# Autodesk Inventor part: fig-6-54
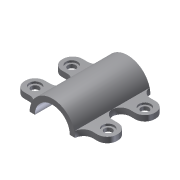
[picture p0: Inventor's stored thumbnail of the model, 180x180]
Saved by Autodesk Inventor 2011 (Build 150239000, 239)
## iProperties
Created: 2004-05
Part Number: fig-6-54
Document SubType Name: Modeling
Designer: CADCIM Technologies
Manufacturer: Standard
Standards Organization: Custom
Density: 1 g/cm^3
Author: CADCIM Technologies
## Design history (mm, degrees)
node "Sketch1"
sketch "Sketch2"
  geometry: L1 (23.378, 0)-(17.996, 0); L2 (-17.996, 0)-(-23.378, 0); A1 r 23.378 centre (0, 0) between (23.378, 0) and (-23.378, 0); A2 r 17.996 centre (0, 0) between (17.996, 0) and (-17.996, 0)
  constraints: 4 end point, 4 point on circle, 2 centre point, 1 collinear, 1 horizontal
extrude "Extrusion1" new body sketch "Sketch2" stored distance "d0" = 38.75; taper "d1" = 0 deg
sketch "Sketch3"
  geometry: L1 (23.378, 0)-(17.996, 0); L2 (-17.996, 0)-(-23.378, 0) reference; L3 (-23.378, 0)-(-47.662, 0); L4 (-47.662, 0)-(-47.662, 5.722); L5 (-47.662, 5.722)-(-22.667, 5.722); A1 r 17.996 centre (0, 0) between (17.996, 0) and (-17.996, 0) reference; A2 r 23.378 centre (0, 0) between (23.378, 0) and (-23.378, 0) reference; 1 further point
  constraints: 10 end point, 5 point on circle, 2 centre point, 1 collinear, 1 horizontal, 1 midpoint, 1 parallel, 1 perpendicular, 3 other
extrude "Extrusion2" join sketch "Sketch3" stored distance "d2" = 21; taper "d3" = 0 deg
fillet "Fillet1" dims "d4" = 10
hole "Hole1" diameter "d7" = 8; stored, may be unused: countersink angle "d11" = 90 deg, drill point angle "d13" = 118 deg; dims "d5" = 10, "d6" = 10, "d8" = 6, "d9" = 12, "d10" = 2, "d12" = 12
fillet "Fillet2" dims "d14" = 9.5
mirror "Mirror1"
mirror "Mirror2"
body "Solid1"
